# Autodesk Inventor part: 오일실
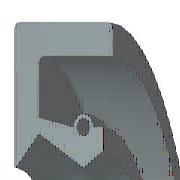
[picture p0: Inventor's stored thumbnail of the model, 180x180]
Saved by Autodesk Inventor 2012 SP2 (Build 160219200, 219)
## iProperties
IsCustomPart: 0
Company: 한국ATC센터
Created: 2014-10
Part Number: 오일실
Material: 고무
Description: 오일-실
Document SubType Name: Modeling
Standard: KS B 2804
Designer: KYOUNG IL JANG
Standards Organization: KS
Language: ko-KR
Size Designation: D - 17 32 8
Categories: <MemberInstance><Categories><Category DisplayName="샤프트 부품" InternalName="7f7aeb1f-a693-4053-b835-cee3144e0d98" Mnemonic="SHFT"><Category DisplayName="실링" Intern
Density: 0.93 g/cm^3
Mass: 2.28027 g
Surface Area: 32.1224 cm^2
Volume: 2.45191 cm^3
Author: KYOUNG IL JANG
Revision Number: 1
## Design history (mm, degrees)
revolve "본체" stored, may be unused: angle "d17" = 90 deg
revolve "스프링1" stored, may be unused: angle "d18" = 90 deg
body "Solid1"
sketch "스케치1"
  geometry: L1 (0, 16)-(8, 16); L2 (8, 14.25)-(1.75, 14.25); L3 (1.75, 10.25)-(4.9, 8.5); L4 (4.9, 8.5)-(0, 8.5); L5 (0, 0)-(9.586, 0) reference; L6 (4.9, 8.5)-(6.3, 9.375); L7 (0, 18)-(0, -3) reference; L8 (-1.941, 0)-(11.507, 0) reference; L9 (4.2, 10.6)-(1.75, 11.21); L10 (1.75, 11.21)-(1.75, 14.25); L11 (0, 16)-(0, 8.588); L12 (4.9, 8.5)-(0, 8.5); L13 (1.75, 10.25)-(0.152, 8.528); L14 (8, 16)-(8, 14.25); L15 (5.6, 10.6)-(6.3, 10.6); L16 (6.3, 10.6)-(6.3, 9.375); C1 r 0.455 at (4.9, 10.6); A1 r 0.7 centre (4.9, 10.6) between (5.6, 10.6) and (4.2, 10.6); A2 r 0.088 centre (0.088, 8.588) between (0, 8.588) and (0.152, 8.528); 1 further point
  constraints: 28 end point, 5 horizontal alignment, 5 point on line, 4 point on circle, 4 vertical alignment, 3 centre point, 3 tangent, 2 collinear, 2 horizontal, 2 perpendicular, 1 coincident, 1 parallel
  dimensions: "d0" = 32 diameter of L1 L5 (= SD2); "d1" = 1.75 distance of L1.end L2.start (= SD); "d2" = 0.91 diameter of C1 (= SPDI); "d3" = 1.4 diameter of A1 (= SPDA); "d4" = 17 diameter of L3.end L5 (= NND); "d5" = 20.5 diameter of L3.start L5 (= TKDM); "d7" = 22.42 diameter of L9.end L5 (= TKDM + 0.24 x SWDT); "d8" = 1.75 distance between parallel lines of L11 L10 (= SD); "d9" = 4.9 distance from line of L11 C1.centre (= SPDST); "d10" = 21.2 diameter of C1.centre L5 (= HLDM); "d11" = 0.0875 radius of A2 (= 0.25 x LAB); "d12" = 6.3 distance between parallel lines of L11 L16 (= SDI); "d13" = 18.75 diameter of L6.end L5 (= ABDM); "d14" = 8 distance from line of L11 L1.end (= SWDT)
fillet "모깎기1" dims "d6" = 0.3 (= RR)
other parameters: "SD2" = 32 [user parameter; used in 1 equation term], "SWDT" = 8 [user parameter; used in 2 equation terms], "RR" = 0.3 [user parameter; used in 1 equation term], "SD" = 1.75 [user parameter; used in 2 equation terms], "NND" = 17 [user parameter; used in 1 equation term], "SPDA" = 1.4 [user parameter; used in 1 equation term], "SPDI" = 0.91 [user parameter; used in 1 equation term], "TKDM" = 20.5 [user parameter; used in 2 equation terms], "HLDM" = 21.2 [user parameter; used in 1 equation term], "ABDM" = 18.75 [user parameter; used in 1 equation term], "SDI" = 6.3 [user parameter; used in 1 equation term], "SPDST" = 4.9 [user parameter; used in 1 equation term], "LAB" = 0.35 [user parameter; used in 1 equation term], "d15" = 0, "d16" = 0, "d19" = 0
